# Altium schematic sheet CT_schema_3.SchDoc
size 513 x 378 mm
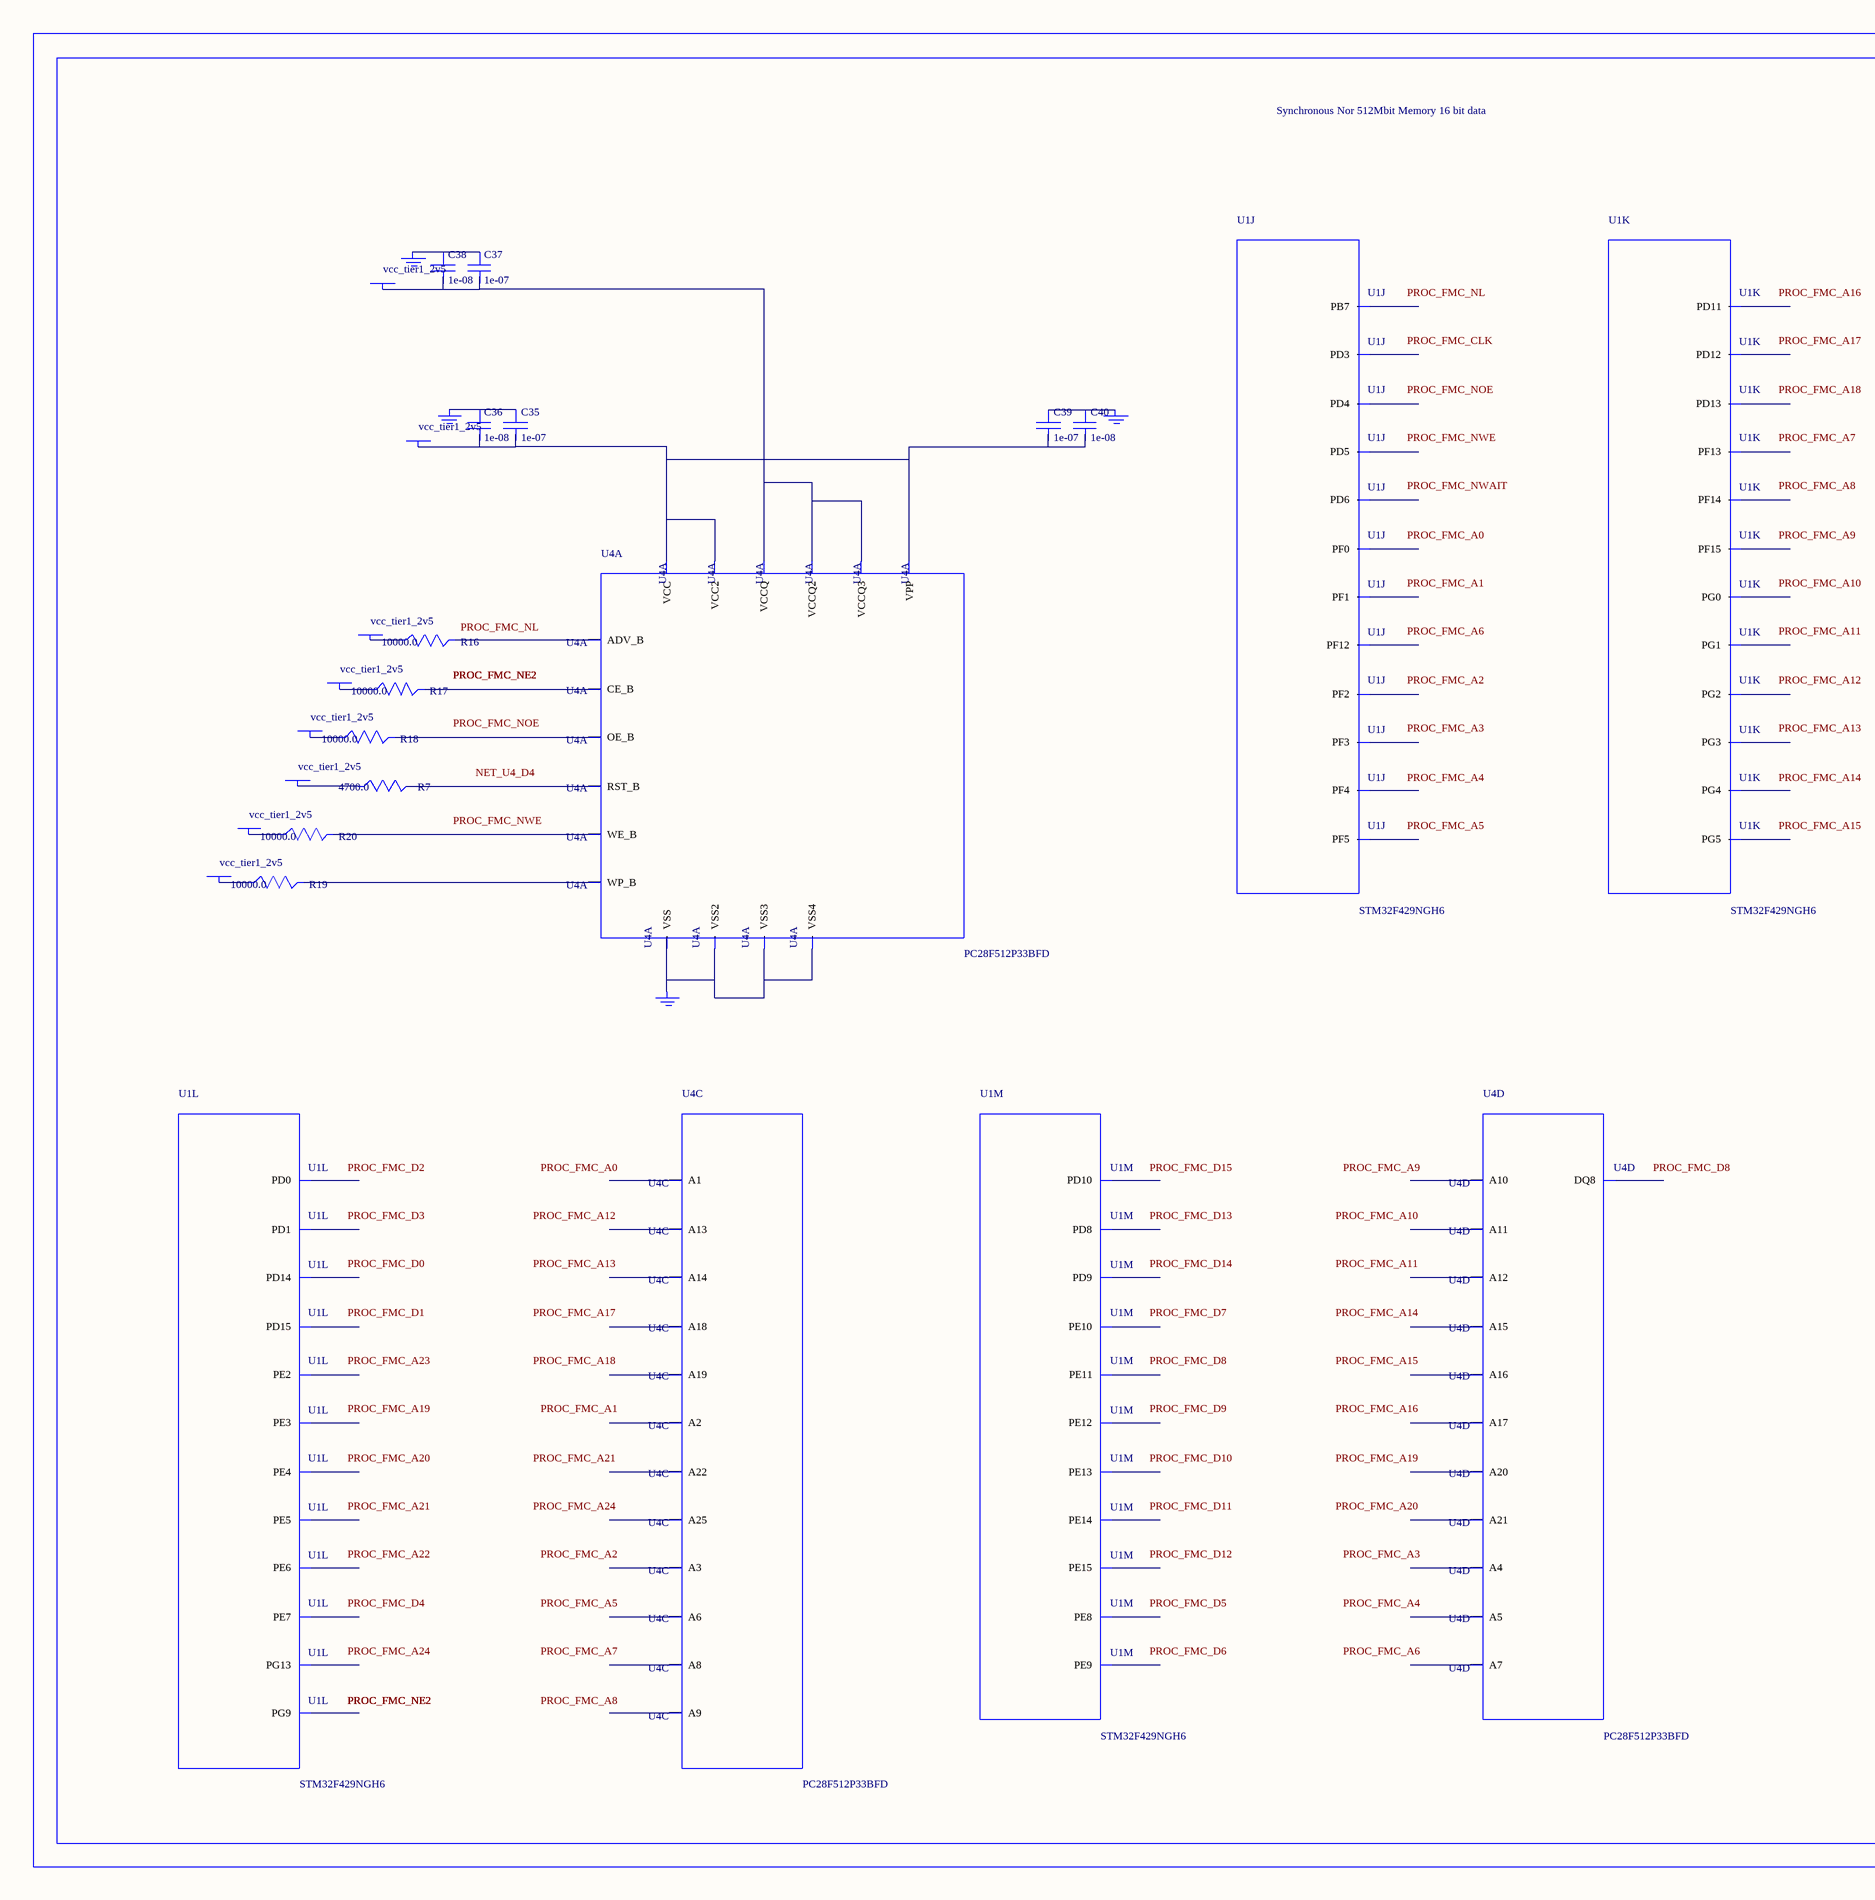
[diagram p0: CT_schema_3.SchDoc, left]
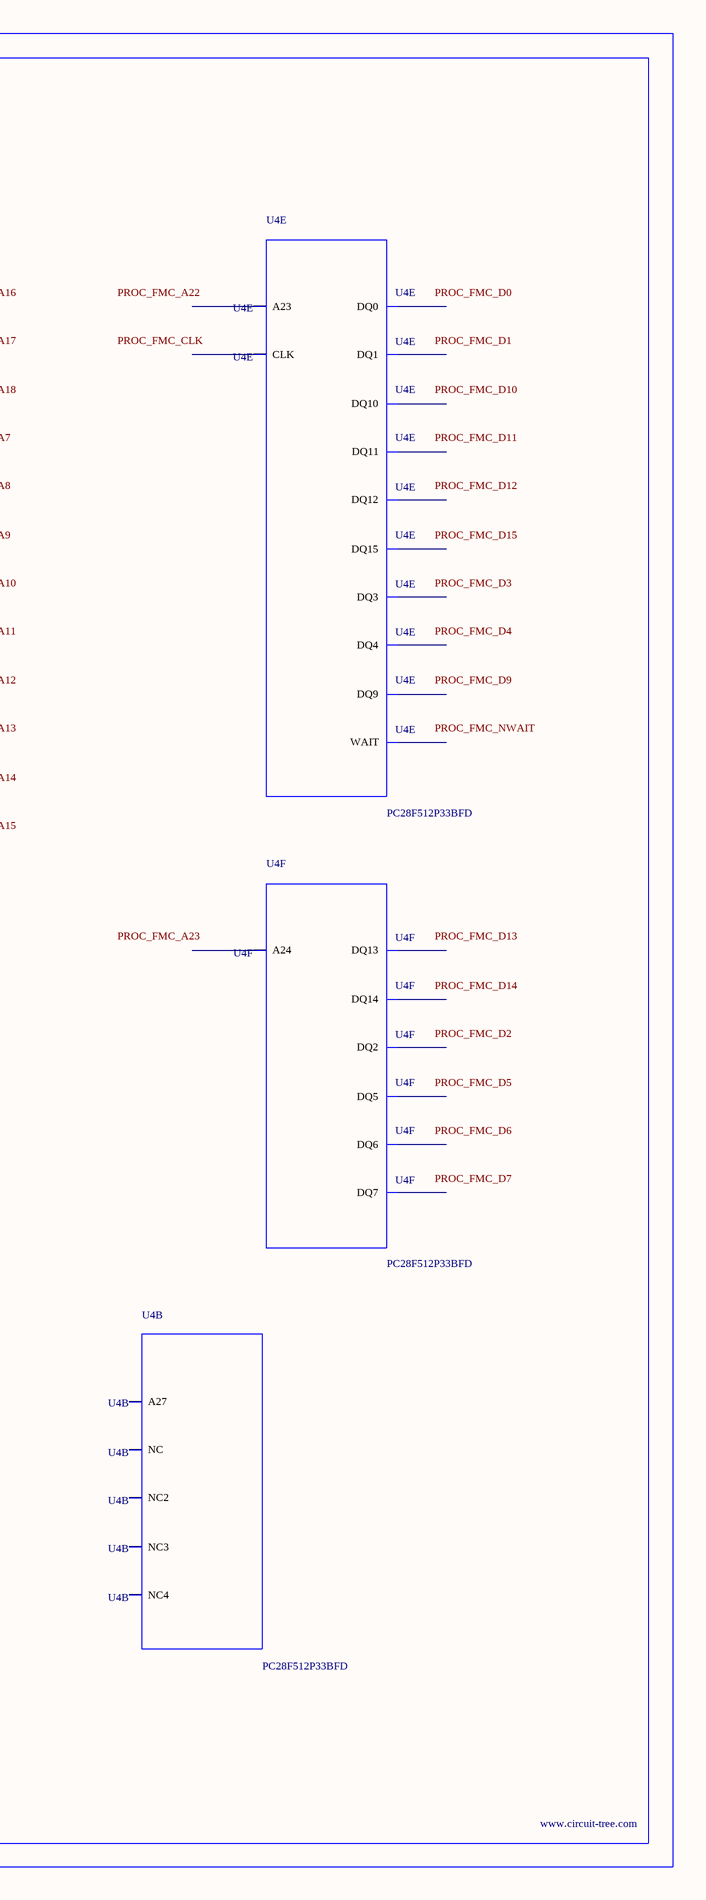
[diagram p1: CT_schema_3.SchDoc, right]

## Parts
BORDER2  (no value)
C35  1e-07  [C0402]
C36  1e-08  [C0402]
C37  1e-07  [C0402]
C38  1e-08  [C0402]
C39  1e-07  [C0402]
C40  1e-08  [C0402]
GND_INSTANCE_2_0  (no value)
GND_INSTANCE_2_1  (no value)
GND_INSTANCE_2_2  (no value)
GND_INSTANCE_2_3  (no value)
POWER_INSTANCE_2_0  vcc_tier1_2v5
POWER_INSTANCE_2_1  vcc_tier1_2v5
POWER_INSTANCE_2_2  vcc_tier1_2v5
POWER_INSTANCE_2_3  vcc_tier1_2v5
POWER_INSTANCE_2_4  vcc_tier1_2v5
POWER_INSTANCE_2_5  vcc_tier1_2v5
POWER_INSTANCE_2_6  vcc_tier1_2v5
POWER_INSTANCE_2_7  vcc_tier1_2v5
R7  4700.0  [R0603]
R16  10000.0  [R0603]
R17  10000.0  [R0603]
R18  10000.0  [R0603]
R19  10000.0  [R0603]
R20  10000.0  [R0603]
U1  STM32F429NGH6  [TFBGA216]  (parts J,K,L,M of 16)
U4  PC28F512P33BFD  [PC28F512P33BFD]  (parts A,B,C,D,E,F of 6)

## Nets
NetC35_1: C35.1 C36.1 GND_INSTANCE_2_0.0(GND)
NetC35_2: C35.2 C36.2 C39.2 C40.2 POWER_INSTANCE_2_0.0(PWR) U4.A4(VPP) U4.A6(VCC) U4.H3(VCC2)
NetC37_1: C37.1 C38.1 GND_INSTANCE_2_1.0(GND)
NetC37_2: C37.2 C38.2 POWER_INSTANCE_2_1.0(PWR) U4.D5(VCCQ) U4.D6(VCCQ2) U4.G4(VCCQ3)
NetC39_1: C39.1 C40.1 GND_INSTANCE_2_2.0(GND)
NetGND_INSTANCE_2_3_0: GND_INSTANCE_2_3.0(GND) U4.B2(VSS) U4.H2(VSS2) U4.H4(VSS3) U4.H6(VSS4)
NetPOWER_INSTANCE_2_2_0: POWER_INSTANCE_2_2.0(PWR) R16.1
NetPOWER_INSTANCE_2_3_0: POWER_INSTANCE_2_3.0(PWR) R17.1
NetPOWER_INSTANCE_2_4_0: POWER_INSTANCE_2_4.0(PWR) R18.1
NetPOWER_INSTANCE_2_5_0: POWER_INSTANCE_2_5.0(PWR) R19.1
NetPOWER_INSTANCE_2_6_0: POWER_INSTANCE_2_6.0(PWR) R20.1
NetPOWER_INSTANCE_2_7_0: POWER_INSTANCE_2_7.0(PWR) R7.1
NetR7_2: R7.2 U4.D4(RST_B)
NetR16_2: R16.2 U4.F6(ADV_B)
NetR17_2: R17.2 U4.B4(CE_B)
NetR18_2: R18.2 U4.F8(OE_B)
NetR19_2: R19.2 U4.C6(WP_B)
NetR20_2: R20.2 U4.G8(WE_B)

Not connected (* = marked no-connect by the designer): U1 A1(PE4) A2(PE3) A3(PE2) B1(PE5) B2(PE6) B3(PG13) B5(PB7) B11(PD6) B12(PD0) C10(PD5) C11(PD3) C12(PD1) D2(PF0) D9(PG9) D11(PD4) E2(PF1) G2(PF2) H2(PF3) J2(PF4) K3(PF5) K13(PD15) K15(PD10) L12(PD14) L14(PD9) L15(PD8) M6(PF12) M7(PG1) M8(PF15) M10(PD12) M11(PD13) M12(PG3) M13(PG2) N6(PF13) N7(PG0) N9(PE8) N10(PD11) N11(PG5) N12(PG4) P6(PF14) P9(PE9) P10(PE11) P11(PE14) R8(PE7) R9(PE10) R10(PE12) R11(PE15) R12(PE13); U4 A1 A2(A6) A3(A8) A5(A13) A7(A18) A8(A22) B1(A2) B3(A9) B5(A14) B6(A25) B7(A19) B8(NC) C1(A3) C2(A7) C3(A10) C4(A12) C5(A15) C7(A20) C8(A21) D1(A4) D2(A5) D3(A11) D7(A16) D8(A17) E1(DQ8) E2(DQ1) E3(DQ9) E4(DQ3) E5(DQ4) E6(CLK) E7(DQ15) E8(NC2) F1(NC3) F2(DQ0) F3(DQ10) F4(DQ11) F5(DQ12) F7(WAIT) G1(A23) G2(NC4) G3(DQ2) G5(DQ5) G6(DQ6) G7(DQ14) H1(A27) H5(DQ13) H7(DQ7) H8(A24)

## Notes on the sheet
- Labels drawn without touching a wire or pin: NET_U4_D4, PROC_FMC_A0, PROC_FMC_A1, PROC_FMC_A2, PROC_FMC_A3, PROC_FMC_A4, PROC_FMC_A5, PROC_FMC_A6, PROC_FMC_A7, PROC_FMC_A8, PROC_FMC_A9, PROC_FMC_A10, PROC_FMC_A11, PROC_FMC_A12, PROC_FMC_A13, PROC_FMC_A14, PROC_FMC_A15, PROC_FMC_A16, PROC_FMC_A17, PROC_FMC_A18, PROC_FMC_A19, PROC_FMC_A20, PROC_FMC_A21, PROC_FMC_A22, PROC_FMC_A23, PROC_FMC_A24, PROC_FMC_CLK, PROC_FMC_D0, PROC_FMC_D1, PROC_FMC_D2, PROC_FMC_D3, PROC_FMC_D4, PROC_FMC_D5, PROC_FMC_D6, PROC_FMC_D7, PROC_FMC_D8, PROC_FMC_D9, PROC_FMC_D10, PROC_FMC_D11, PROC_FMC_D12, PROC_FMC_D13, PROC_FMC_D14, PROC_FMC_D15, PROC_FMC_NL, PROC_FMC_NOE, PROC_FMC_NWAIT, PROC_FMC_NWE

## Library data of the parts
BORDER2 = BORDER_PAGE2
C35 C37 C39 = C0402C104K3RACTU
C36 C38 C40 = C0402C103K3RAC
GND_INSTANCE_2_0-GND_INSTANCE_2_3 = GND
POWER_INSTANCE_2_0-POWER_INSTANCE_2_7 = PWR
R7 = RC0603JR-074K7L
R16-R20 = RC0603JR-0710KL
